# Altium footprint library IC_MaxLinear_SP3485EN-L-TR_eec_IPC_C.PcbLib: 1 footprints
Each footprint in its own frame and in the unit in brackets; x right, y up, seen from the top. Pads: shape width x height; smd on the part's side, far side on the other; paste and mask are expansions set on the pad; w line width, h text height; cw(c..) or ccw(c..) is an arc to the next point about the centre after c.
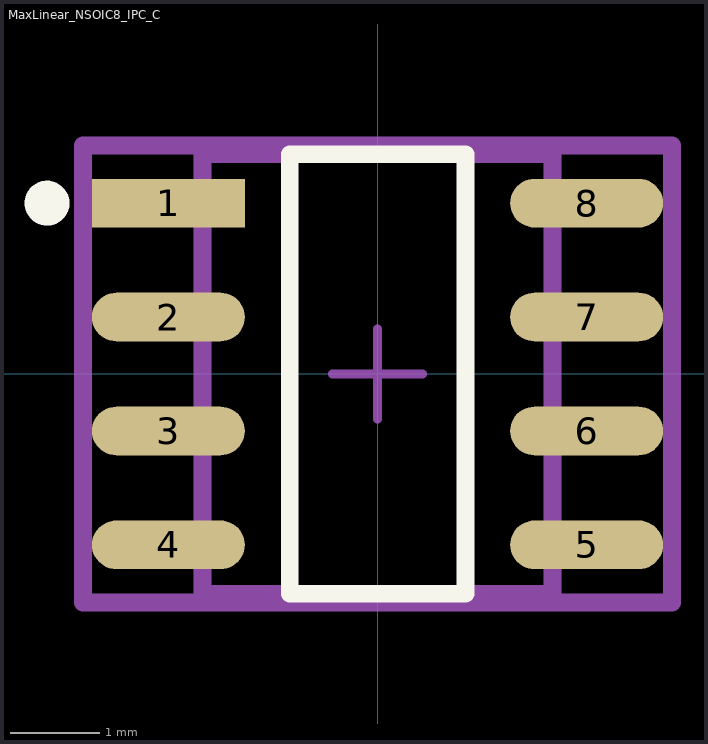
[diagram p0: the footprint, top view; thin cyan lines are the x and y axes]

## MaxLinear_NSOIC8_IPC_C [mil]
pads (8):
  rect 67.18x21.34 smd paste+0 mask+0: 1(-91.82,75)
  rrect100% 67.18x21.34 smd paste+0 mask+0: 2(-91.82,25) 3(-91.82,-25) 4(-91.82,-75) 5(91.82,-75) 6(91.82,-25) 7(91.82,25) 8(91.82,75)
Top Overlay:
  circle w9.84: c-145.09,75 r4.92
  lines w7.87: -38.54,-96.46 38.54,-96.46 38.54,96.46 -38.54,96.46 -38.54,-96.46
Mechanical 10:
  lines w7.87: -129.34,-100.39 129.34,-100.39 129.34,100.39 -129.34,100.39 -129.34,-100.39
  text ".Designator" at 0,7.41 h39.37
Mechanical 12:
  lines w7.87: -76.77,-96.46 76.77,-96.46 76.77,96.46 -76.77,96.46 -76.77,-96.46
Mechanical 15:
  lines w3.94: -19.68,0 19.68,0 ; 0,-19.68 0,19.68
  lines w7.87: -129.34,-100.39 129.34,-100.39 129.34,100.39 -129.34,100.39 -129.34,-100.39
3D body "IC_MaxLinear_SP3485EN-L-TR_eec.STEP": height 10, standoff 0, extent -129.34,-100.39 129.34,100.39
